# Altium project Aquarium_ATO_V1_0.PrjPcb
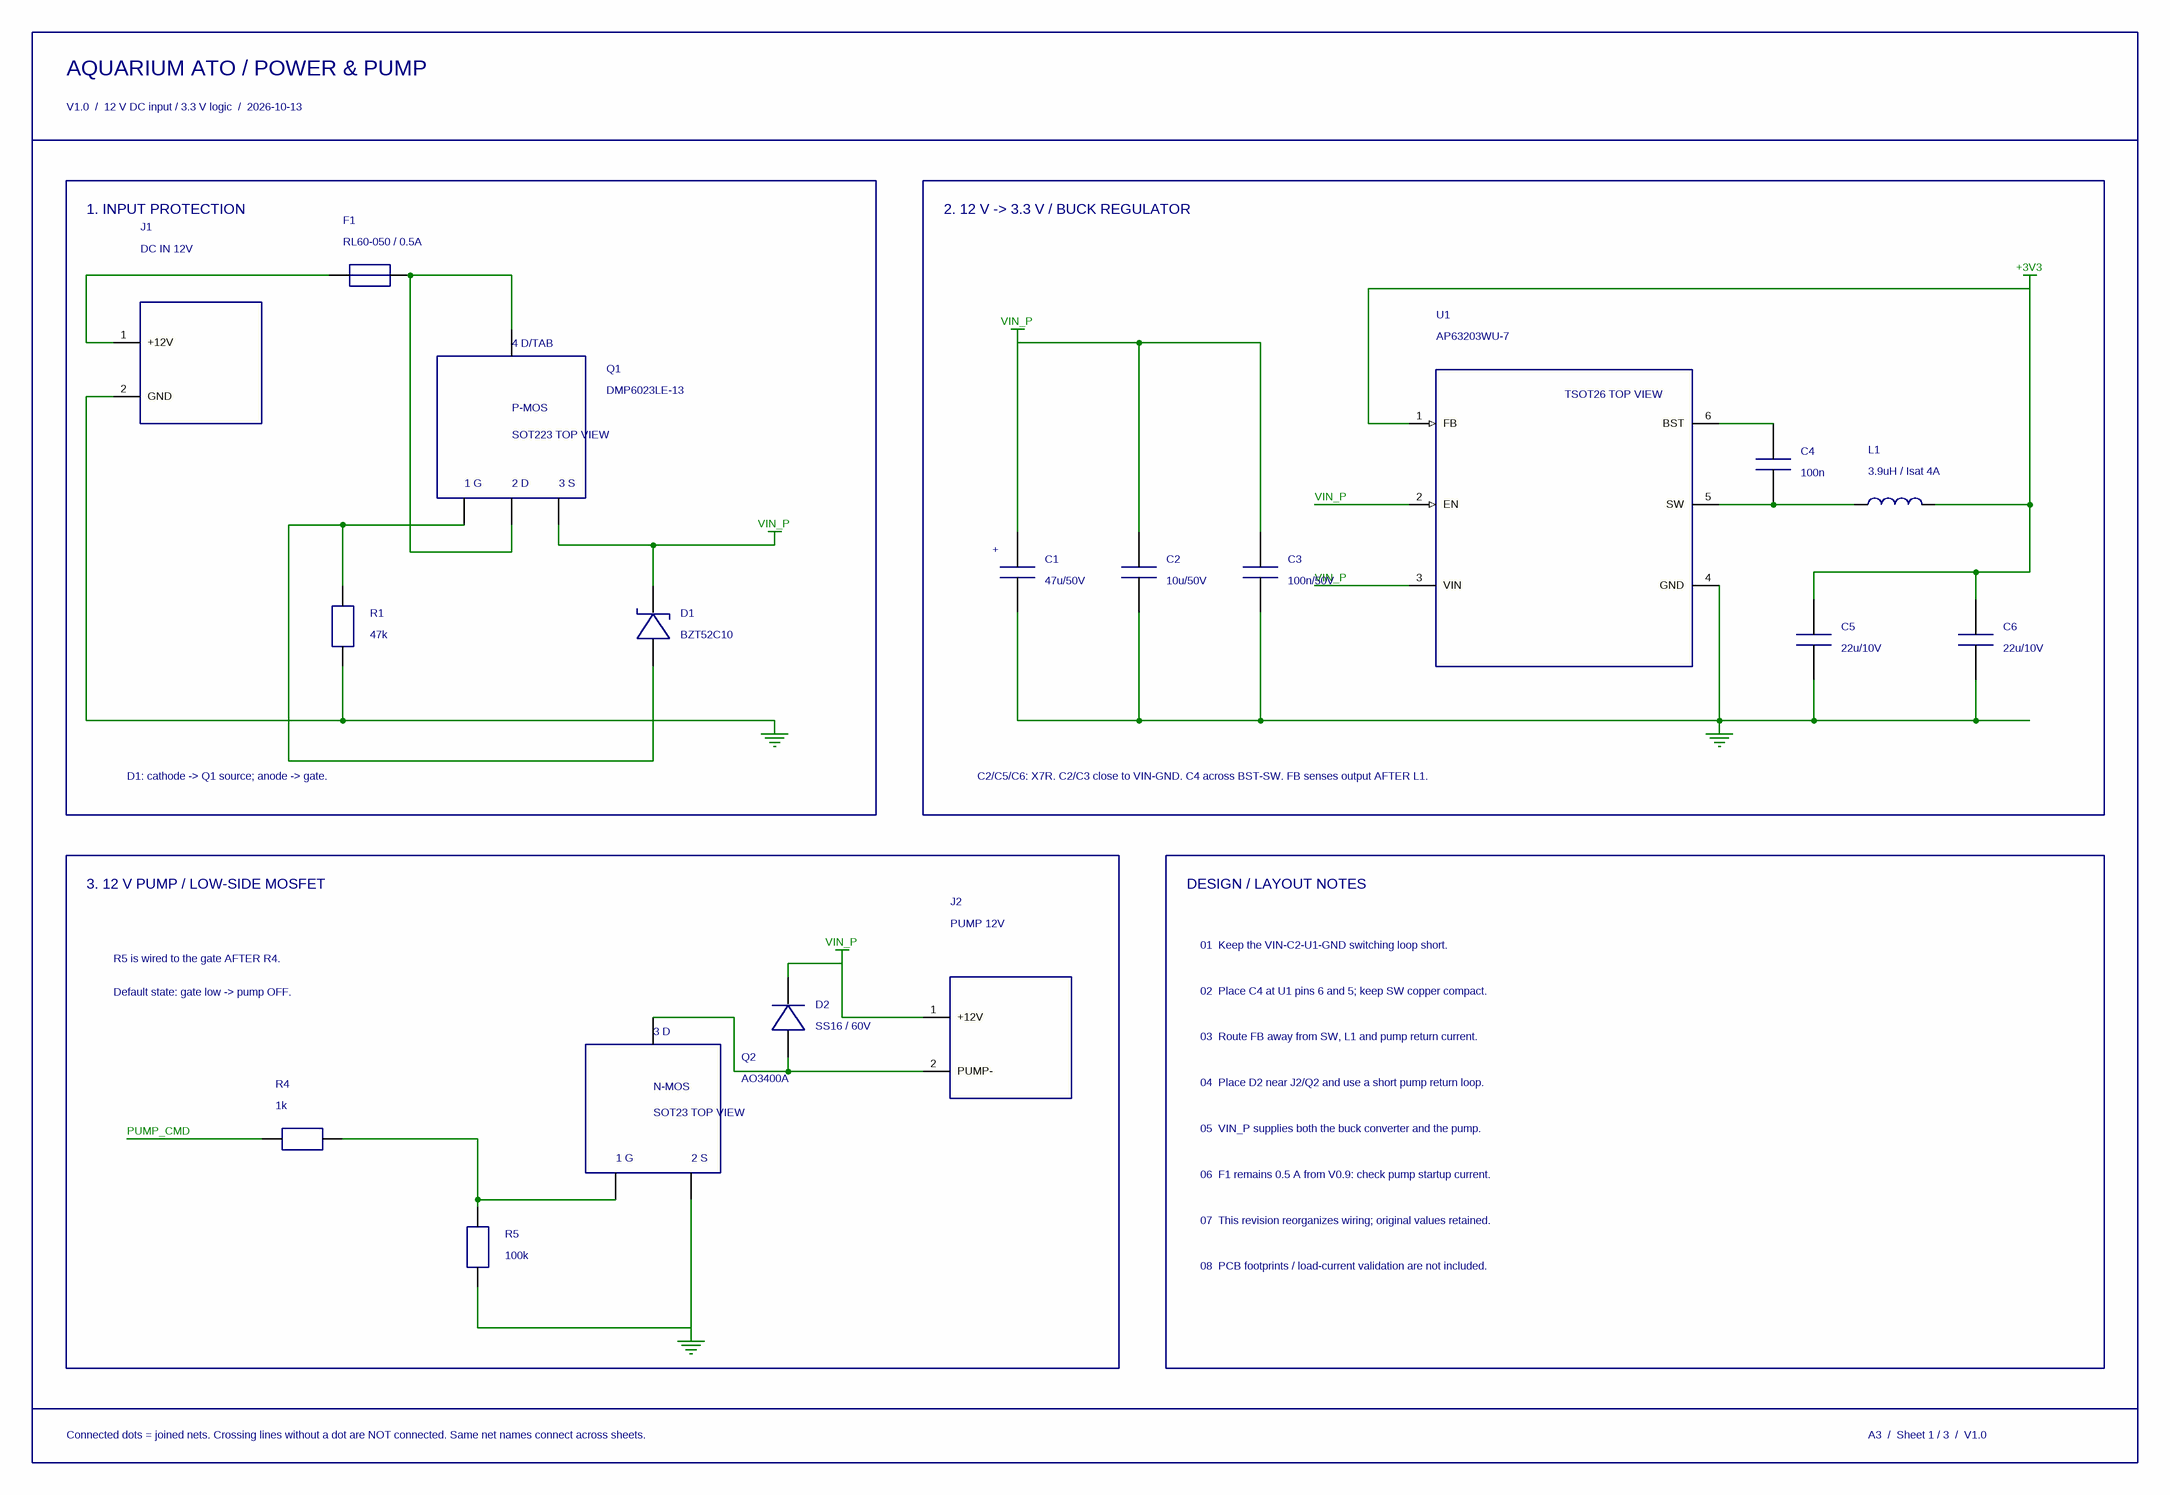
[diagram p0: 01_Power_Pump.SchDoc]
3 sheets, 64 parts. Net scope: global (net labels, ports and power ports of the same name join across sheets).
Board file: Aquarium_ATO_V1_0_LCEDA.PcbDoc
Sheets:
  01_Power_Pump.SchDoc
  02_Controller_IO.SchDoc
  03_Sensors.SchDoc

## Sheet 01_Power_Pump.SchDoc
size 406 x 279 mm

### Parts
C1  47u/50V  [CP_RADIAL_D8.0_P3.50]
C2  10u/50V  [C_1210_3225Metric]
C3  100n/50V  [C_0603_1608Metric]
C4  100n  [C_0603_1608Metric]
C5  22u/10V  [C_0805_2012Metric]
C6  22u/10V  [C_0805_2012Metric]
D1  BZT52C10  [SOD-123]
D2  SS16 / 60V  [D_SMA]
F1  RL60-050 / 0.5A  [PPTC_RADIAL_P5.10_D8.0]
J1  DC IN 12V  [TB_2P_P5.08]
J2  PUMP 12V  [TB_2P_P5.08]
L1  3.9uH / Isat 4A  [IND_SMD_6.0x6.0]
Q1  DMP6023LE-13  [SOT-223-4]
Q2  AO3400A  [SOT-23-3]
R1  47k  [R_0603_1608Metric]
R4  1k  [R_0603_1608Metric]
R5  100k  [R_0603_1608Metric]
U1  AP63203WU-7  [TSOT-23-6_P0.95]

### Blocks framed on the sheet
1. INPUT PROTECTION: D1 F1 J1 Q1 R1
2. 12 V -> 3.3 V / BUCK REGULATOR: C1-C6 L1 U1
3. 12 V PUMP / LOW-SIDE MOSFET: D2 J2 Q2 R4 R5

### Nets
+3V3: C5.1 C6.1 L1.2 U1.1(FB)
GND: C1.2 C2.2 C3.2 C5.2 C6.2 J1.2(GND) Q2.2(S) R1.2 R5.2 U1.4(GND)
VIN_P: C1.1 C2.1 C3.1 D1.1(K) D2.1(K) J2.1(+12V) Q1.3(S) U1.2(EN) U1.3(VIN)
PUMP_CMD: R4.1
NetC4_1: C4.1 U1.6(BST)
NetC4_2: C4.2 L1.1 U1.5(SW)
NetD1_2: D1.2(A) Q1.1(G) R1.1
NetD2_2: D2.2(A) J2.2(PUMP-) Q2.3(D)
NetF1_1: F1.1 J1.1(+12V)
NetF1_2: F1.2 Q1.2(D) Q1.4(D_/_TAB)
NetQ2_1: Q2.1(G) R4.2 R5.1

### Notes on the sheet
- AQUARIUM ATO / POWER & PUMP
- V1.0  /  12 V DC input / 3.3 V logic  /  2026-10-13
- D1: cathode -> Q1 source; anode -> gate.
- C2/C5/C6: X7R. C2/C3 close to VIN-GND. C4 across BST-SW. FB senses output AFTER L1.
- DESIGN / LAYOUT NOTES
- R5 is wired to the gate AFTER R4.
- 01  Keep the VIN-C2-U1-GND switching loop short.
- Default state: gate low -> pump OFF.
- 02  Place C4 at U1 pins 6 and 5; keep SW copper compact.
- 03  Route FB away from SW, L1 and pump return current.
- 04  Place D2 near J2/Q2 and use a short pump return loop.
- 05  VIN_P supplies both the buck converter and the pump.
- 06  F1 remains 0.5 A from V0.9: check pump startup current.
- 07  This revision reorganizes wiring; original values retained.
- 08  PCB footprints / load-current validation are not included.
- Connected dots = joined nets. Crossing lines without a dot are NOT connected. Same net names connect across sheets.
- A3  /  Sheet 1 / 3  /  V1.0

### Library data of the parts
C1 = CAPACITOR_POLARIZED_RADIAL: 47u/50V; footprint CP_RADIAL_D8.0_P3.50
C2 = CAPACITOR_C_1210_3225METRIC: 10u/50V; footprint C_1210_3225Metric
C3 = CAPACITOR_C_0603_1608METRIC: 100n/50V; footprint C_0603_1608Metric
C4 = CAPACITOR_C_0603_1608METRIC: 100n; footprint C_0603_1608Metric
C5 C6 = CAPACITOR_C_0805_2012METRIC: 22u/10V; footprint C_0805_2012Metric
D1 = ZENER_DIODE: BZT52C10; package SOD-123; footprint SOD-123
D2 = DIODE: SS16 / 60V; package SMA; footprint D_SMA
F1 = PTC_RESETTABLE_FUSE: RL60-050 / 0.5A; package Radial leaded PPTC; footprint PPTC_RADIAL_P5.10_D8.0
J1 = DC_INPUT_2P: DC IN 12V; footprint TB_2P_P5.08
J2 = PUMP_OUTPUT_2P: PUMP 12V; footprint TB_2P_P5.08
L1 = INDUCTOR_6X6: 3.9uH / Isat 4A; footprint IND_SMD_6.0x6.0
Q1 = PMOS_DMP6023LE: DMP6023LE-13; package SOT223 (tab/pad 4 = drain); footprint SOT-223-4
Q2 = NMOS_AO3400A: AO3400A; package SOT23; footprint SOT-23-3
R1 = RESISTOR_0603: 47k; footprint R_0603_1608Metric
R4 = RESISTOR_0603: 1k; footprint R_0603_1608Metric
R5 = RESISTOR_0603: 100k; footprint R_0603_1608Metric
U1 = AP63203WU_7: AP63203WU-7; package TSOT26; footprint TSOT-23-6_P0.95

## Sheet 02_Controller_IO.SchDoc
size 406 x 279 mm
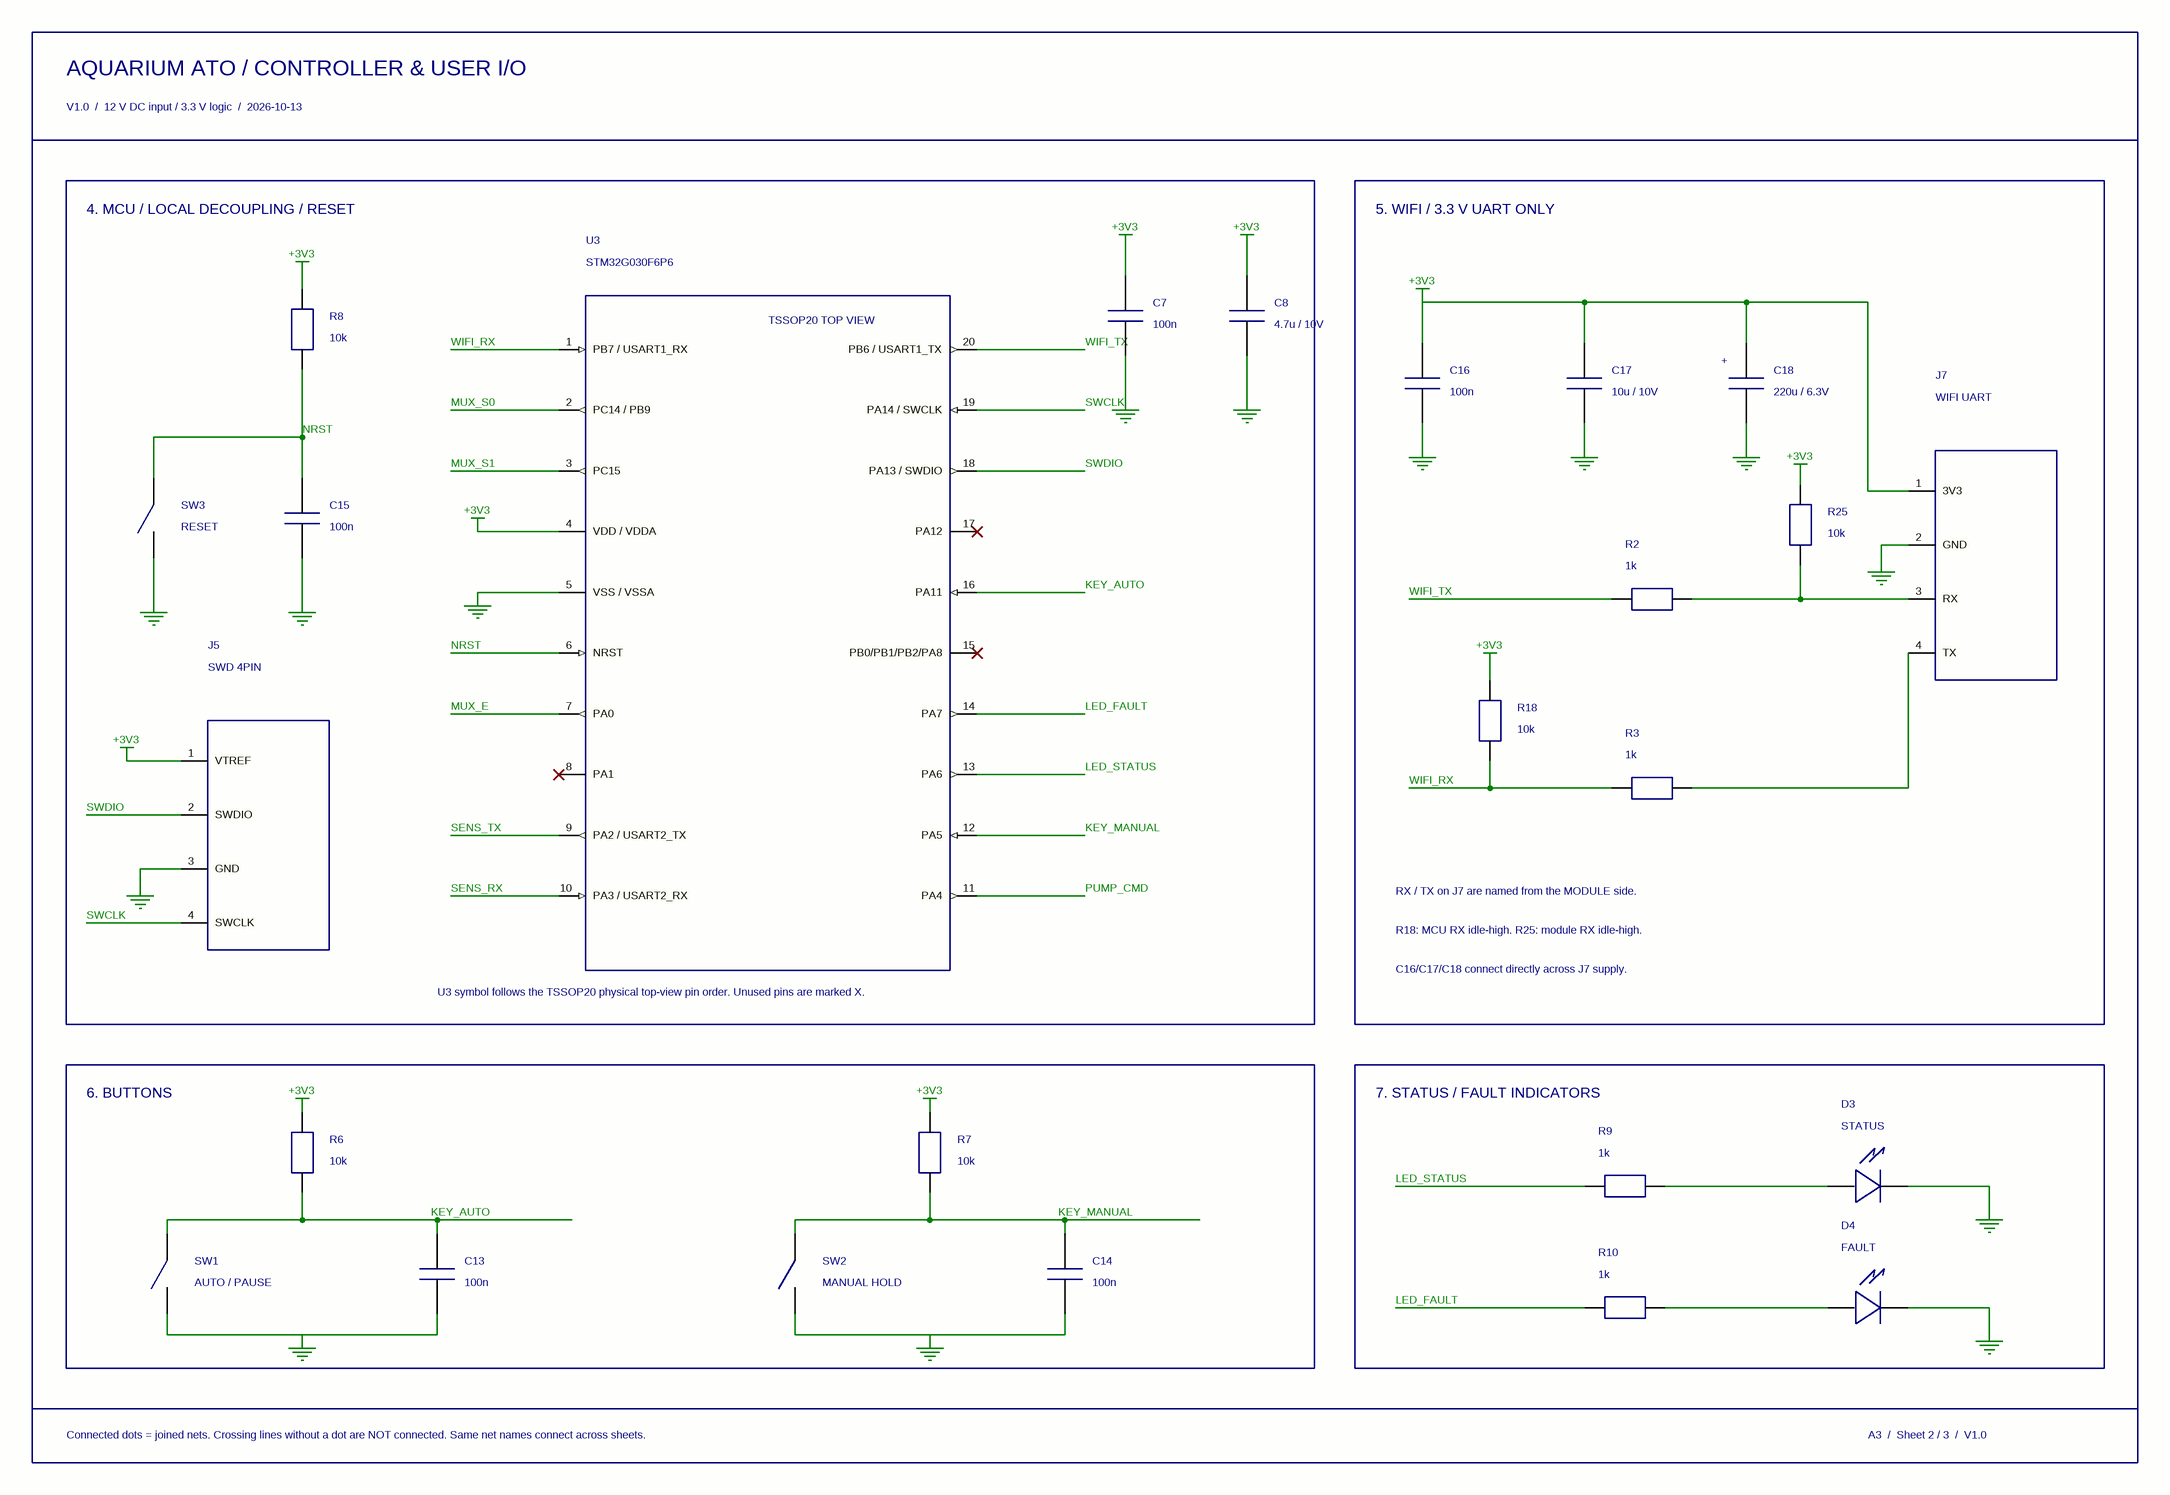
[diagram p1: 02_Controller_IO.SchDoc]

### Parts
C7  100n  [C_0603_1608Metric]
C8  4.7u / 10V  [C_0805_2012Metric]
C13  100n  [C_0603_1608Metric]
C14  100n  [C_0603_1608Metric]
C15  100n  [C_0603_1608Metric]
C16  100n  [C_0603_1608Metric]
C17  10u / 10V  [C_0805_2012Metric]
C18  220u / 6.3V  [CP_RADIAL_D8.0_P3.50]
D3  STATUS  [LED_0603_1608Metric]
D4  FAULT  [LED_0603_1608Metric]
J5  SWD 4PIN  [HDR_1x4_P2.54]
J7  WIFI UART  [HDR_1x4_P2.54]
R2  1k  [R_0603_1608Metric]
R3  1k  [R_0603_1608Metric]
R6  10k  [R_0603_1608Metric]
R7  10k  [R_0603_1608Metric]
R8  10k  [R_0603_1608Metric]
R9  1k  [R_0603_1608Metric]
R10  1k  [R_0603_1608Metric]
R18  10k  [R_0603_1608Metric]
R25  10k  [R_0603_1608Metric]
SW1  AUTO / PAUSE  [SW_TACT_6x6_4P]
SW2  MANUAL HOLD  [SW_TACT_6x6_4P]
SW3  RESET  [SW_TACT_6x6_4P]
U3  STM32G030F6P6  [TSSOP-20_P0.65]

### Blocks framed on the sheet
4. MCU / LOCAL DECOUPLING / RESET: C7 C8 C15 J5 R8 SW3 U3
5. WIFI / 3.3 V UART ONLY: C16-C18 J7 R2 R3 R18 R25
6. BUTTONS: C13 C14 R6 R7 SW1 SW2
7. STATUS / FAULT INDICATORS: D3 D4 R9 R10

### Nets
+3V3: C7.1 C8.1 C16.1 C17.1 C18.1 J5.1(VTREF) J7.1(3V3) R6.1 R7.1 R8.1 R18.1 R25.1 U3.4(VDD_/_VDDA)
GND: C7.2 C8.2 C13.2 C14.2 C15.2 C16.2 C17.2 C18.2 D3.1(K) D4.1(K) J5.3(GND) J7.2(GND) SW1.2 SW2.2 SW3.2 U3.5(VSS_/_VSSA)
KEY_AUTO: C13.1 R6.2 SW1.1 U3.16(PA11)
KEY_MANUAL: C14.1 R7.2 SW2.1 U3.12(PA5)
LED_FAULT: R10.1 U3.14(PA7)
LED_STATUS: R9.1 U3.13(PA6)
MUX_E: U3.7(PA0)
MUX_S0: U3.2(PC14_/_PB9)
MUX_S1: U3.3(PC15)
NRST: C15.1 R8.2 SW3.1 U3.6(NRST)
PUMP_CMD: U3.11(PA4)
SENS_RX: U3.10(PA3_/_USART2_RX)
SENS_TX: U3.9(PA2_/_USART2_TX)
SWCLK: J5.4(SWCLK) U3.19(PA14_/_SWCLK)
SWDIO: J5.2(SWDIO) U3.18(PA13_/_SWDIO)
WIFI_RX: R3.1 R18.2 U3.1(PB7_/_USART1_RX)
WIFI_TX: R2.1 U3.20(PB6_/_USART1_TX)
NetD3_2: D3.2(A) R9.2
NetD4_2: D4.2(A) R10.2
NetJ7_3: J7.3(RX) R2.2 R25.2
NetJ7_4: J7.4(TX) R3.2

Not connected (* = marked no-connect by the designer): U3 8(PA1)* 15(PB0/PB1/PB2/PA8)* 17(PA12)*

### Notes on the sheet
- AQUARIUM ATO / CONTROLLER & USER I/O
- V1.0  /  12 V DC input / 3.3 V logic  /  2026-10-13
- RX / TX on J7 are named from the MODULE side.
- R18: MCU RX idle-high. R25: module RX idle-high.
- C16/C17/C18 connect directly across J7 supply.
- U3 symbol follows the TSSOP20 physical top-view pin order. Unused pins are marked X.
- Connected dots = joined nets. Crossing lines without a dot are NOT connected. Same net names connect across sheets.
- A3  /  Sheet 2 / 3  /  V1.0

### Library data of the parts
C7 C13-C16 = CAPACITOR_C_0603_1608METRIC: 100n; footprint C_0603_1608Metric
C8 = CAPACITOR_C_0805_2012METRIC: 4.7u / 10V; footprint C_0805_2012Metric
C17 = CAPACITOR_C_0805_2012METRIC: 10u / 10V; footprint C_0805_2012Metric
C18 = CAPACITOR_POLARIZED_RADIAL: 220u / 6.3V; footprint CP_RADIAL_D8.0_P3.50
D3 = LED_0603: STATUS; footprint LED_0603_1608Metric
D4 = LED_0603: FAULT; footprint LED_0603_1608Metric
J5 = SWD_4P: SWD 4PIN; footprint HDR_1x4_P2.54
J7 = WIFI_UART_4P: WIFI UART; footprint HDR_1x4_P2.54
R2 R3 R9 R10 = RESISTOR_0603: 1k; footprint R_0603_1608Metric
R6-R8 R18 R25 = RESISTOR_0603: 10k; footprint R_0603_1608Metric
SW1 = SWITCH_TACT_6X6: AUTO / PAUSE; footprint SW_TACT_6x6_4P
SW2 = SWITCH_TACT_6X6: MANUAL HOLD; footprint SW_TACT_6x6_4P
SW3 = SWITCH_TACT_6X6: RESET; footprint SW_TACT_6x6_4P
U3 = STM32G030F6P6: STM32G030F6P6; package TSSOP20; footprint TSSOP-20_P0.65

## Sheet 03_Sensors.SchDoc
size 406 x 279 mm
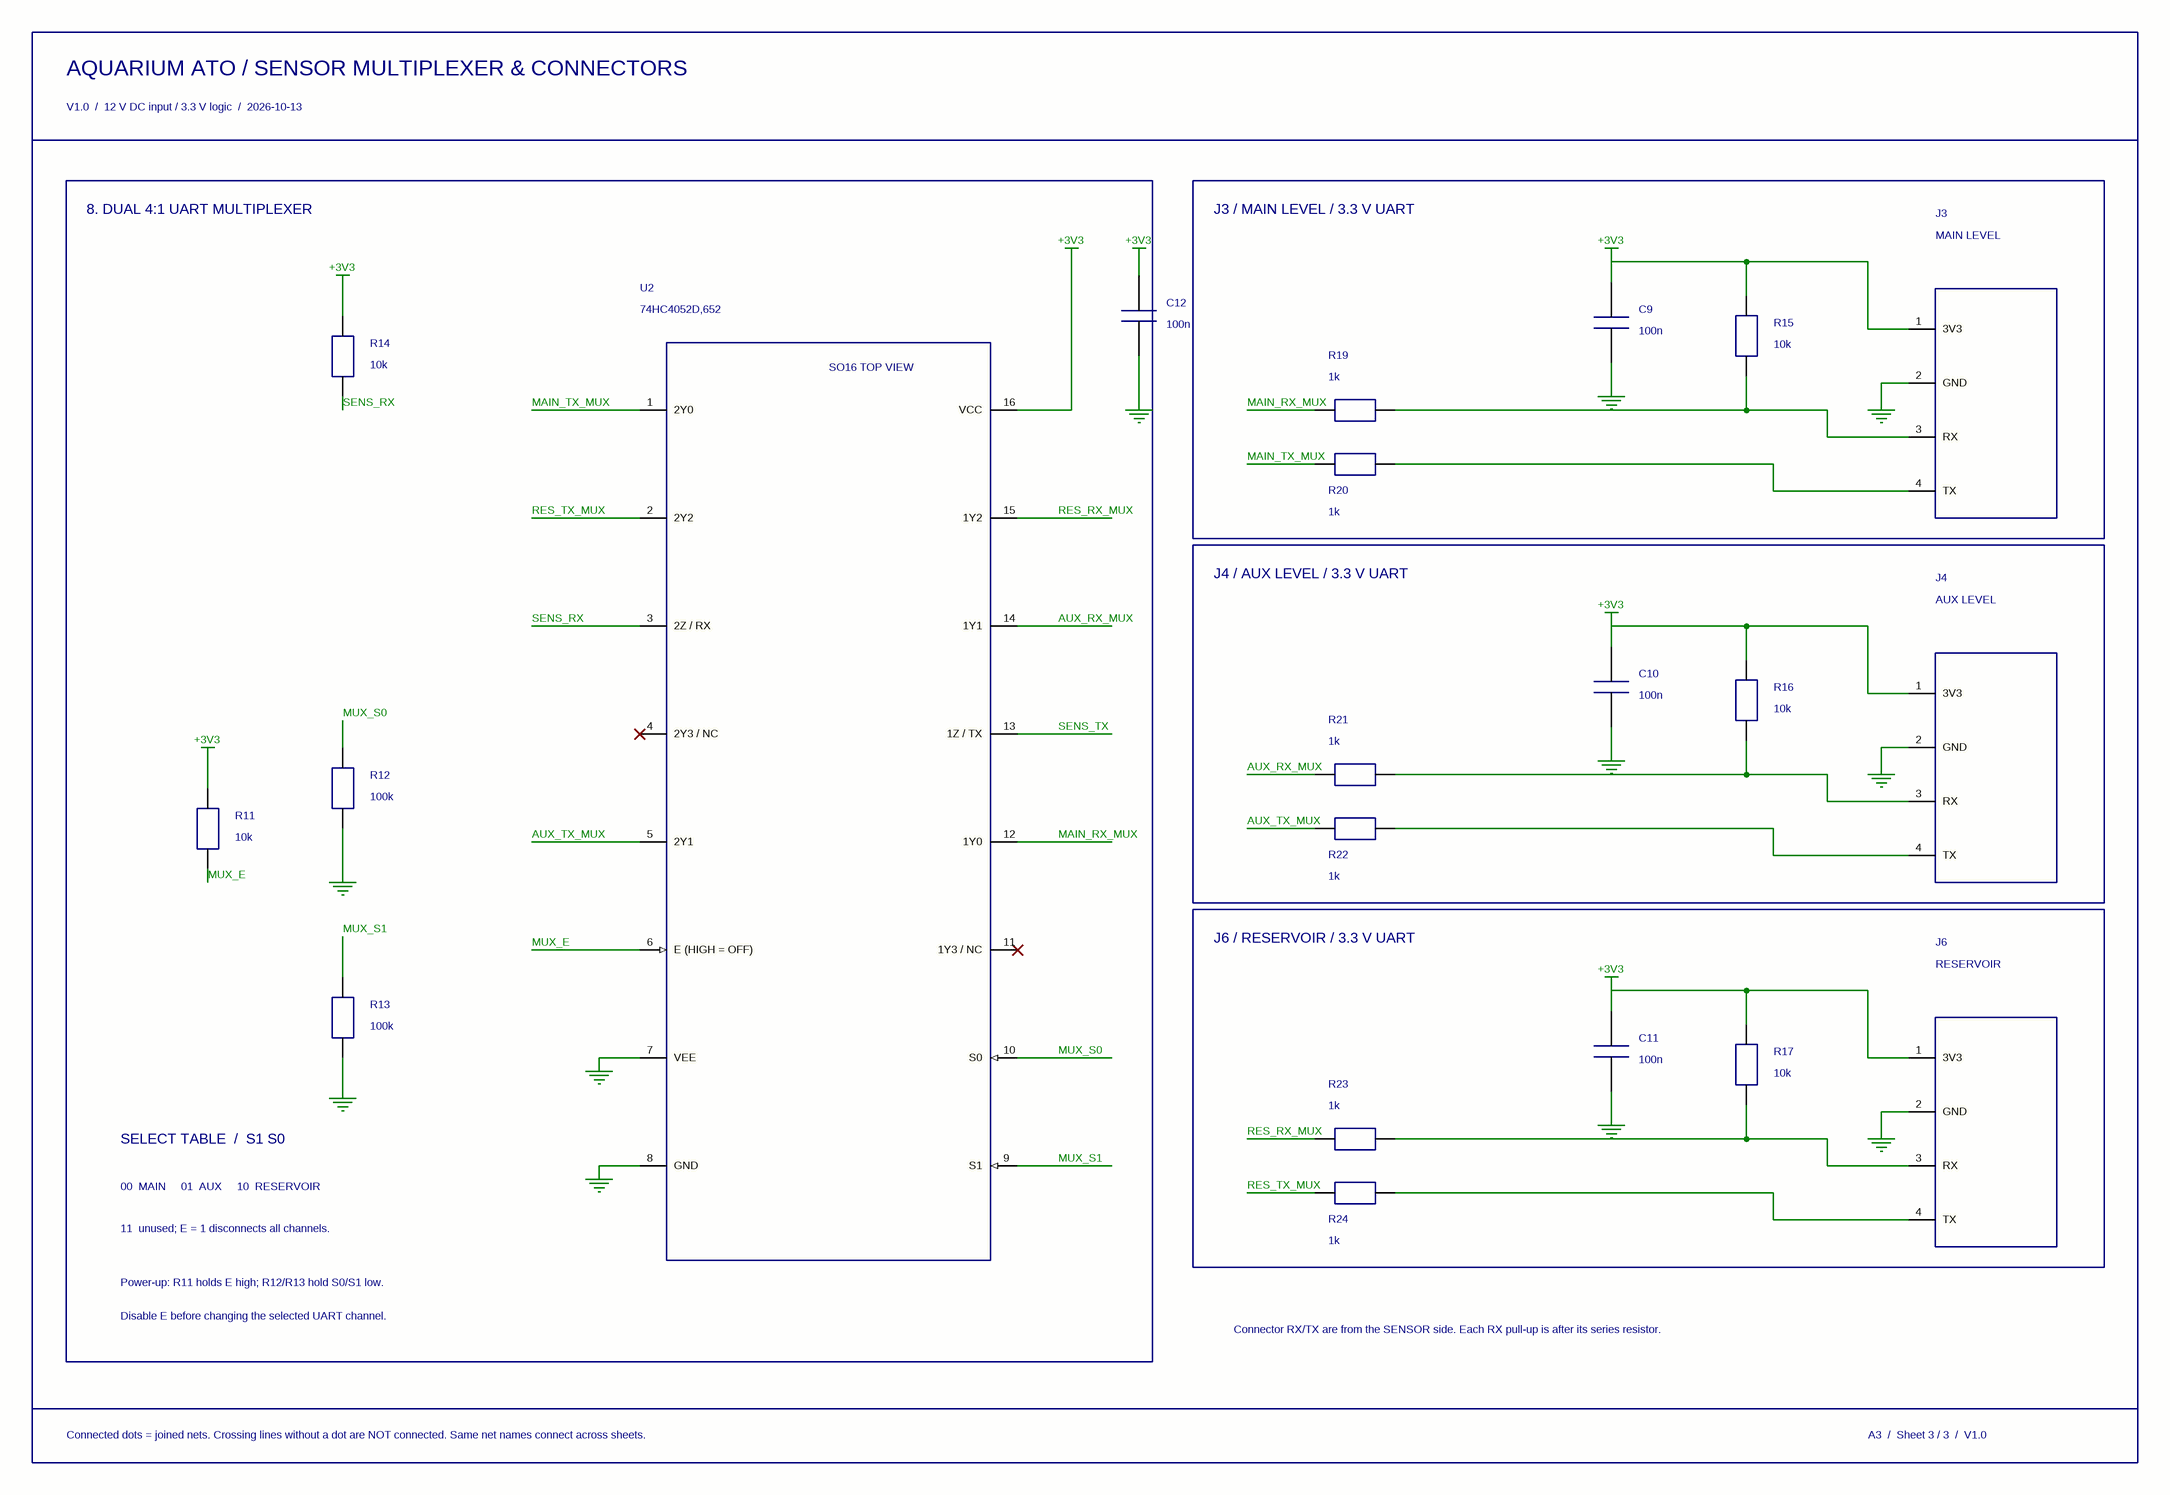
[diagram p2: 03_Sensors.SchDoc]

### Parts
C9  100n  [C_0603_1608Metric]
C10  100n  [C_0603_1608Metric]
C11  100n  [C_0603_1608Metric]
C12  100n  [C_0603_1608Metric]
J3  MAIN LEVEL  [HDR_1x4_P2.54]
J4  AUX LEVEL  [HDR_1x4_P2.54]
J6  RESERVOIR  [HDR_1x4_P2.54]
R11  10k  [R_0603_1608Metric]
R12  100k  [R_0603_1608Metric]
R13  100k  [R_0603_1608Metric]
R14  10k  [R_0603_1608Metric]
R15  10k  [R_0603_1608Metric]
R16  10k  [R_0603_1608Metric]
R17  10k  [R_0603_1608Metric]
R19  1k  [R_0603_1608Metric]
R20  1k  [R_0603_1608Metric]
R21  1k  [R_0603_1608Metric]
R22  1k  [R_0603_1608Metric]
R23  1k  [R_0603_1608Metric]
R24  1k  [R_0603_1608Metric]
U2  74HC4052D,652  [SOIC-16_P1.27]

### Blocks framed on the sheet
J3 / MAIN LEVEL / 3.3 V UART: C9 J3 R15 R19 R20
J4 / AUX LEVEL / 3.3 V UART: C10 J4 R16 R21 R22
J6 / RESERVOIR / 3.3 V UART: C11 J6 R17 R23 R24

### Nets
+3V3: C9.1 C10.1 C11.1 C12.1 J3.1(3V3) J4.1(3V3) J6.1(3V3) R11.1 R14.1 R15.1 R16.1 R17.1 U2.16(VCC)
GND: C9.2 C10.2 C11.2 C12.2 J3.2(GND) J4.2(GND) J6.2(GND) R12.2 R13.2 U2.7(VEE) U2.8(GND)
AUX_RX_MUX: R21.1 U2.14(1Y1)
AUX_TX_MUX: R22.1 U2.5(2Y1)
MAIN_RX_MUX: R19.1 U2.12(1Y0)
MAIN_TX_MUX: R20.1 U2.1(2Y0)
MUX_E: R11.2 U2.6(E_(HIGH_=_OFF))
MUX_S0: R12.1 U2.10(S0)
MUX_S1: R13.1 U2.9(S1)
RES_RX_MUX: R23.1 U2.15(1Y2)
RES_TX_MUX: R24.1 U2.2(2Y2)
SENS_RX: R14.2 U2.3(2Z_/_RX)
SENS_TX: U2.13(1Z_/_TX)
NetJ3_3: J3.3(RX) R15.2 R19.2
NetJ3_4: J3.4(TX) R20.2
NetJ4_3: J4.3(RX) R16.2 R21.2
NetJ4_4: J4.4(TX) R22.2
NetJ6_3: J6.3(RX) R17.2 R23.2
NetJ6_4: J6.4(TX) R24.2

Not connected (* = marked no-connect by the designer): U2 4(2Y3_/_NC)* 11(1Y3_/_NC)*

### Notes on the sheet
- AQUARIUM ATO / SENSOR MULTIPLEXER & CONNECTORS
- V1.0  /  12 V DC input / 3.3 V logic  /  2026-10-13
- 8. DUAL 4:1 UART MULTIPLEXER
- SELECT TABLE  /  S1 S0
- 00  MAIN     01  AUX     10  RESERVOIR
- 11  unused; E = 1 disconnects all channels.
- Power-up: R11 holds E high; R12/R13 hold S0/S1 low.
- Disable E before changing the selected UART channel.
- Connector RX/TX are from the SENSOR side. Each RX pull-up is after its series resistor.
- Connected dots = joined nets. Crossing lines without a dot are NOT connected. Same net names connect across sheets.
- A3  /  Sheet 3 / 3  /  V1.0

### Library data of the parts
C9-C12 = CAPACITOR_C_0603_1608METRIC: 100n; footprint C_0603_1608Metric
J3 = SENSOR_UART_4P: MAIN LEVEL; footprint HDR_1x4_P2.54
J4 = SENSOR_UART_4P: AUX LEVEL; footprint HDR_1x4_P2.54
J6 = SENSOR_UART_4P: RESERVOIR; footprint HDR_1x4_P2.54
R11 R14-R17 = RESISTOR_0603: 10k; footprint R_0603_1608Metric
R12 R13 = RESISTOR_0603: 100k; footprint R_0603_1608Metric
R19-R24 = RESISTOR_0603: 1k; footprint R_0603_1608Metric
U2 = 74HC4052D: 74HC4052D,652; package SO16 (SOT109-1); footprint SOIC-16_P1.27

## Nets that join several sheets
+3V3: 01_Power_Pump (C5.1 C6.1 L1.2 U1.1), 02_Controller_IO (13 pins), 03_Sensors (13 pins)
GND: 01_Power_Pump (10 pins), 02_Controller_IO (16 pins), 03_Sensors (11 pins)
MUX_E: 02_Controller_IO (U3.7), 03_Sensors (R11.2 U2.6)
MUX_S0: 02_Controller_IO (U3.2), 03_Sensors (R12.1 U2.10)
MUX_S1: 02_Controller_IO (U3.3), 03_Sensors (R13.1 U2.9)
PUMP_CMD: 01_Power_Pump (R4.1), 02_Controller_IO (U3.11)
SENS_RX: 02_Controller_IO (U3.10), 03_Sensors (R14.2 U2.3)
SENS_TX: 02_Controller_IO (U3.9), 03_Sensors (U2.13)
